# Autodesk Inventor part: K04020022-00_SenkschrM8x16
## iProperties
Created: 2006-09
Part Number: K04020022-00_SenkschrM8x16
Material: Stahl
Document SubType Name: Modeling
Designer: Anwender
Author: Anwender
SBm.TeileNr: -
SBm.TeileRev: 00
SBm.Rohteil: -
SBm.Werkstoff: -
SBm.WerkstNr: -
SBm.Gewicht: 0.0
SBm.BenennD: Deu
SBm.BenennE: Eng
SBm.AenIndex1: 0.0
SBm.AenDatum1: 2006-03-31
SBm.AenName1: -
SBm.AenIndex2: 0.0
SBm.AenDatum2: 2006-03-31
SBm.AenName2: -
SBm.InvVersion: 10.0
SBm.EntstAus: -
SBm.Groesse: -
SBm.Hersteller: -
SBm.Norm: -
SBm.ZchgFormat: -
